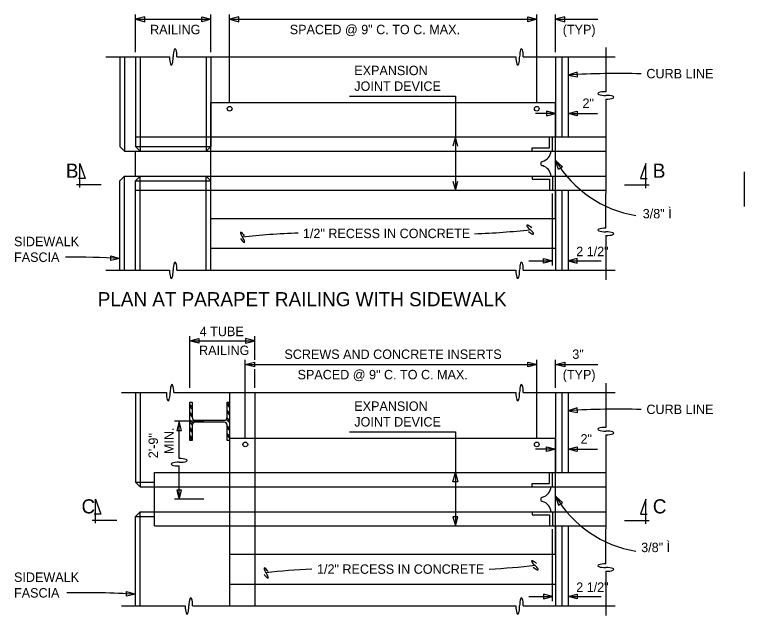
# Model space of a CAD drawing. Extents: x 19590 to 20151, y 19944 to 20103.
# Drawn here: x 19613.3 to 19649.19, y 20048.4 to 20077.92 of the extents above; entities that cross this region are included whole.
import ezdxf

# ---------------------------------------------------------------- set-up
doc = ezdxf.new("R2010")
doc.units = 0
for name, color, linetype in [('DETAIL_PR', 7, 'Continuous'), ('DETAIL_TEXT_DIMEN_PR', 7, 'Continuous'), ('Level 1', 7, 'Continuous'), ('Sheet_Label_Str_Wt0', 7, 'Continuous')]:
    doc.layers.add(name, color=color, linetype=linetype)

msp = doc.modelspace()

# ---------------------------------------------------------------- linework, layer by layer
at = {"layer": 'DETAIL_PR'}
for p, q in [((19642.377, 20076.299), (19642.377, 20074.13)), ((19617.788, 20075.837), (19620.92, 20075.837)), ((19618.481, 20075.837), (19618.481, 20071.443)), ((19618.712, 20075.837), (19618.712, 20071.212)), ((19619.252, 20075.837), (19619.252, 20071.443)), ((19619.483, 20075.837), (19619.483, 20071.212)), ((19621.284, 20075.837), (19637.956, 20075.837)), ((19622.721, 20075.837), (19622.721, 20071.212)), ((19622.952, 20075.837), (19622.952, 20071.443)), ((19638.32, 20075.837), (19642.84, 20075.837)), ((19639.91, 20075.837), (19639.91, 20071.906)), ((19640.219, 20075.837), (19640.219, 20071.906)), ((19640.527, 20075.837), (19640.527, 20071.906)), ((19622.952, 20067.897), (19622.952, 20073.602)), ((19622.952, 20073.602), (19639.91, 20073.602)), ((19639.91, 20067.897), (19639.91, 20073.602)), ((19642.377, 20073.766), (19642.377, 20069.131)), ((19619.252, 20071.906), (19639.91, 20071.906)), ((19639.602, 20071.366), (19639.602, 20071.906)), ((19639.756, 20071.212), (19639.756, 20071.906)), ((19639.91, 20071.906), (19642.377, 20071.906)), ((19618.713, 20071.212), (19618.481, 20071.443)), ((19619.252, 20071.443), (19622.952, 20071.443)), ((19619.483, 20071.212), (19619.252, 20071.443)), ((19622.952, 20071.443), (19622.721, 20071.212)), ((19618.712, 20071.212), (19622.721, 20071.212)), ((19619.252, 20069.979), (19619.252, 20071.212)), ((19622.721, 20071.212), (19642.377, 20071.212)), ((19638.754, 20071.212), (19638.754, 20071.366)), ((19638.754, 20071.366), (19639.602, 20071.366)), ((19649.195, 20068.492), (19649.195, 20070.188)), ((19618.713, 20069.978), (19618.481, 20069.747)), ((19618.481, 20065.354), (19618.481, 20069.747)), ((19618.712, 20069.979), (19622.721, 20069.979)), ((19618.712, 20065.354), (19618.712, 20069.979)), ((19619.483, 20069.978), (19619.252, 20069.747)), ((19619.252, 20069.747), (19622.952, 20069.747)), ((19619.252, 20065.354), (19619.252, 20069.747)), ((19619.483, 20065.354), (19619.483, 20069.979)), ((19622.721, 20069.979), (19642.377, 20069.979)), ((19622.721, 20065.354), (19622.721, 20069.979)), ((19622.952, 20069.747), (19622.721, 20069.979)), ((19622.952, 20065.354), (19622.952, 20069.747)), ((19638.754, 20069.979), (19638.754, 20069.825)), ((19638.754, 20069.824), (19639.602, 20069.824)), ((19639.602, 20069.825), (19639.602, 20069.285)), ((19639.756, 20069.979), (19639.756, 20069.285)), ((19619.252, 20069.285), (19639.91, 20069.285)), ((19639.91, 20069.285), (19639.91, 20065.354)), ((19639.91, 20069.285), (19642.377, 20069.285)), ((19640.219, 20069.285), (19640.219, 20065.354)), ((19640.527, 20069.285), (19640.527, 20065.354)), ((19642.377, 20067.424), (19642.377, 20069.131)), ((19622.952, 20067.897), (19639.91, 20067.897)), ((19642.377, 20067.06), (19642.377, 20064.891)), ((19622.952, 20066.433), (19639.91, 20066.433)), ((19617.788, 20065.353), (19620.92, 20065.353)), ((19621.284, 20065.354), (19637.956, 20065.354)), ((19638.32, 20065.354), (19642.84, 20065.354)), ((19642.377, 20059.804), (19642.377, 20057.634)), ((19618.558, 20059.341), (19620.766, 20059.341)), ((19619.252, 20059.341), (19619.252, 20054.947)), ((19619.483, 20059.341), (19619.483, 20054.716)), ((19621.13, 20059.341), (19637.956, 20059.341)), ((19623.877, 20059.341), (19623.877, 20048.858)), ((19625.11, 20059.341), (19625.11, 20048.858)), ((19638.32, 20059.341), (19642.84, 20059.341)), ((19639.91, 20059.341), (19639.91, 20055.41)), ((19640.219, 20059.341), (19640.219, 20055.41)), ((19640.527, 20059.341), (19640.527, 20055.41)), ((19622.039, 20058.64), (19621.911, 20058.765)), ((19622.039, 20058.539), (19621.911, 20058.677)), ((19623.75, 20058.841), (19623.877, 20058.715)), ((19623.75, 20058.753), (19623.877, 20058.614)), ((19622.039, 20058.161), (19621.911, 20058.299)), ((19622.039, 20058.249), (19621.912, 20058.387)), ((19623.75, 20058.375), (19623.877, 20058.236)), ((19623.751, 20058.463), (19623.878, 20058.337)), ((19622.039, 20057.782), (19621.911, 20057.921)), ((19622.077, 20057.846), (19621.912, 20058.01)), ((19622.165, 20057.984), (19623.623, 20057.984)), ((19623.623, 20057.883), (19622.165, 20057.883)), ((19623.878, 20057.858), (19623.712, 20058.022)), ((19623.75, 20058.085), (19623.877, 20057.947)), ((19622.039, 20057.493), (19621.911, 20057.631)), ((19622.039, 20057.405), (19621.911, 20057.543)), ((19623.75, 20057.707), (19623.878, 20057.568)), ((19623.75, 20057.619), (19623.877, 20057.48)), ((19622.039, 20057.115), (19621.911, 20057.254)), ((19622.039, 20057.027), (19621.911, 20057.153)), ((19623.75, 20057.329), (19623.878, 20057.19)), ((19623.75, 20057.229), (19623.877, 20057.102)), ((19623.877, 20057.106), (19625.11, 20057.106)), ((19625.11, 20057.106), (19639.91, 20057.106)), ((19639.91, 20051.402), (19639.91, 20057.106)), ((19642.377, 20057.271), (19642.377, 20052.635)), ((19620.177, 20052.789), (19620.177, 20055.41)), ((19620.177, 20055.41), (19623.877, 20055.41)), ((19623.877, 20055.41), (19639.91, 20055.41)), ((19639.602, 20054.87), (19639.602, 20055.41)), ((19639.756, 20054.716), (19639.756, 20055.41)), ((19639.91, 20055.41), (19642.377, 20055.41)), ((19619.252, 20054.947), (19620.177, 20054.947)), ((19619.483, 20054.716), (19619.252, 20054.947)), ((19619.483, 20054.716), (19620.177, 20054.716)), ((19620.177, 20054.716), (19623.877, 20054.716)), ((19623.877, 20054.716), (19625.11, 20054.716)), ((19625.11, 20054.716), (19639.91, 20054.716)), ((19638.754, 20054.716), (19638.754, 20054.87)), ((19638.754, 20054.87), (19639.602, 20054.87)), ((19639.91, 20054.716), (19642.377, 20054.716)), ((19619.483, 20053.483), (19619.252, 20053.251)), ((19619.252, 20053.251), (19620.177, 20053.251)), ((19619.252, 20048.858), (19619.252, 20053.251)), ((19619.483, 20053.483), (19620.177, 20053.483)), ((19619.483, 20048.858), (19619.483, 20053.483)), ((19620.177, 20053.483), (19623.877, 20053.483)), ((19623.877, 20053.483), (19625.11, 20053.483)), ((19625.11, 20053.483), (19639.91, 20053.483)), ((19638.754, 20053.483), (19638.754, 20053.329)), ((19638.754, 20053.329), (19639.602, 20053.329)), ((19639.602, 20053.329), (19639.602, 20052.789)), ((19639.756, 20053.483), (19639.756, 20052.789)), ((19639.91, 20053.483), (19642.377, 20053.483)), ((19620.177, 20052.789), (19623.877, 20052.789)), ((19623.877, 20052.789), (19639.91, 20052.789)), ((19639.91, 20052.789), (19642.377, 20052.789)), ((19639.91, 20052.789), (19639.91, 20048.858)), ((19640.219, 20052.789), (19640.219, 20048.858)), ((19640.527, 20052.789), (19640.527, 20048.858)), ((19642.377, 20050.928), (19642.377, 20052.635)), ((19623.877, 20051.402), (19625.11, 20051.402)), ((19625.11, 20051.402), (19639.91, 20051.402)), ((19642.377, 20050.564), (19642.377, 20048.395)), ((19623.877, 20049.937), (19625.11, 20049.937)), ((19625.11, 20049.937), (19639.91, 20049.937)), ((19618.558, 20048.858), (19621.691, 20048.858)), ((19622.055, 20048.858), (19637.956, 20048.858)), ((19638.32, 20048.858), (19642.84, 20048.858))]:
    msp.add_line(p, q, dxfattribs=at)
for points in [[(19622.039, 20057.77), (19622.039, 20056.989), (19621.911, 20056.989), (19621.911, 20058.879), (19622.039, 20058.879), (19622.039, 20058.097)], [(19623.751, 20058.097), (19623.75, 20058.879), (19623.877, 20058.879), (19623.877, 20056.989), (19623.75, 20056.989), (19623.75, 20057.77)]]:
    msp.add_lwpolyline(points, dxfattribs=at)
for centre in [(19623.877, 20073.293), (19638.985, 20073.293), (19624.648, 20056.797), (19638.985, 20056.797)]:
    msp.add_circle(centre, 0.116, dxfattribs=at)
for centre, radius, start, end in [((19639.08, 20071.277), 0.612, 288.1365, 353.9316), ((19639.278, 20070.595), 0.0999, 94.4387, 265.5613), ((19639.08, 20069.914), 0.612, 6.0684, 71.8635), ((19639.08, 20054.781), 0.612, 288.1365, 353.9316), ((19639.278, 20054.1), 0.0999, 94.4387, 265.5613), ((19639.08, 20053.418), 0.612, 6.0684, 71.8635)]:
    msp.add_arc(centre, radius, start, end, dxfattribs=at)
for centre, major_axis, ratio, start_param, end_param in [((19621.193, 20075.837), (0, -0.395), 0.230204, 1.570796, 4.712389), ((19638.229, 20075.837), (0, -0.395), 0.230204, 1.570796, 4.712389), ((19621.011, 20075.837), (0, -0.395), 0.230206, 4.712389, 7.853982), ((19638.047, 20075.837), (0, -0.395), 0.230206, 4.712389, 7.853982), ((19642.377, 20074.039), (0.395, 0), 0.230204, 1.570796, 4.712389), ((19642.377, 20073.857), (0.395, 0), 0.230206, 4.712389, 7.853982), ((19638.697, 20067.398), (0.203, -0.168), 0.230204, 1.570796, 4.712389), ((19624.563, 20067.012), (0.147, -0.219), 0.230204, 1.570796, 4.712389), ((19638.619, 20067.305), (0.203, -0.168), 0.230206, 4.712389, 7.853982), ((19642.377, 20067.333), (0.395, 0), 0.230204, 1.570796, 4.712389), ((19642.377, 20067.151), (0.395, 0), 0.230206, 4.712389, 7.853982), ((19624.462, 20066.945), (0.147, -0.219), 0.230206, 4.712389, 7.853982), ((19621.193, 20065.353), (0, -0.395), 0.230204, 1.570796, 4.712389), ((19638.229, 20065.354), (0, -0.395), 0.230204, 1.570796, 4.712389), ((19621.011, 20065.353), (0, -0.395), 0.230206, 4.712389, 7.853982), ((19638.047, 20065.354), (0, -0.395), 0.230206, 4.712389, 7.853982), ((19621.039, 20059.341), (0, -0.395), 0.230204, 1.570796, 4.712389), ((19638.229, 20059.341), (0, -0.395), 0.230204, 1.570796, 4.712389), ((19620.857, 20059.341), (0, -0.395), 0.230206, 4.712389, 7.853982), ((19638.047, 20059.341), (0, -0.395), 0.230206, 4.712389, 7.853982), ((19622.16, 20058.098), (0.116, 0), 0.993605, 3.141593, 4.712389), ((19622.16, 20057.771), (0.116, 0), 0.993605, 1.570796, 3.141593), ((19623.629, 20058.098), (0.116, 0), 0.993605, 4.712389, 6.283185), ((19623.629, 20057.771), (0.116, 0), 0.993605, 0, 1.570796), ((19642.377, 20057.543), (0.395, 0), 0.230204, 1.570796, 4.712389), ((19642.377, 20057.362), (0.395, 0), 0.230206, 4.712389, 7.853982), ((19638.928, 20050.902), (0.203, -0.168), 0.230204, 1.570796, 4.712389), ((19625.719, 20050.516), (0.147, -0.219), 0.230204, 1.570796, 4.712389), ((19638.851, 20050.809), (0.203, -0.168), 0.230206, 4.712389, 7.853982), ((19642.377, 20050.837), (0.395, 0), 0.230204, 1.570796, 4.712389), ((19642.377, 20050.655), (0.395, 0), 0.230206, 4.712389, 7.853982), ((19625.619, 20050.449), (0.147, -0.219), 0.230206, 4.712389, 7.853982), ((19621.964, 20048.858), (0, -0.395), 0.230204, 1.570796, 4.712389), ((19638.229, 20048.858), (0, -0.395), 0.230204, 1.570796, 4.712389), ((19621.782, 20048.858), (0, -0.395), 0.230206, 4.712389, 7.853982), ((19638.047, 20048.858), (0, -0.395), 0.230206, 4.712389, 7.853982)]:
    msp.add_ellipse(centre, major_axis=major_axis, ratio=ratio, start_param=start_param, end_param=end_param, dxfattribs=at)
at = {"layer": 'DETAIL_TEXT_DIMEN_PR'}
for p, q in [((19619.252, 20076.068), (19619.252, 20077.918)), ((19622.952, 20076.068), (19622.952, 20077.918)), ((19623.877, 20073.602), (19623.877, 20077.918)), ((19638.985, 20073.602), (19638.985, 20077.918)), ((19639.91, 20076.068), (19639.91, 20077.918)), ((19619.252, 20077.687), (19622.952, 20077.687)), ((19623.877, 20077.687), (19638.985, 20077.687)), ((19639.91, 20077.687), (19641.992, 20077.687)), ((19629.765, 20073.91), (19634.977, 20073.91)), ((19634.977, 20073.91), (19634.977, 20069.285)), ((19639.91, 20073.062), (19638.928, 20073.062)), ((19640.527, 20073.062), (19641.972, 20073.062)), ((19616.516, 20069.424), (19616.516, 20070.595)), ((19616.516, 20070.595), (19616.768, 20069.859)), ((19644.343, 20070.595), (19644.089, 20069.859)), ((19644.342, 20069.397), (19644.343, 20070.595)), ((19616.768, 20069.859), (19616.438, 20069.859)), ((19644.089, 20069.859), (19644.42, 20069.859)), ((19617.556, 20069.555), (19616.35, 20069.555)), ((19643.302, 20069.555), (19644.518, 20069.555)), ((19639.756, 20065.585), (19639.756, 20069.131)), ((19638.6, 20065.816), (19639.756, 20065.816)), ((19640.527, 20065.816), (19642.146, 20065.816)), ((19621.911, 20059.572), (19621.911, 20062.116)), ((19625.11, 20060.96), (19625.11, 20062.116)), ((19621.911, 20061.885), (19625.11, 20061.885)), ((19624.648, 20057.106), (19624.648, 20060.96)), ((19624.648, 20060.729), (19638.985, 20060.729)), ((19638.985, 20057.106), (19638.985, 20060.96)), ((19639.91, 20059.572), (19639.91, 20060.96)), ((19639.91, 20060.729), (19641.992, 20060.729)), ((19625.11, 20059.572), (19625.11, 20060.497)), ((19622.6, 20057.934), (19621.16, 20057.934)), ((19621.392, 20056.102), (19621.392, 20057.934)), ((19629.765, 20057.414), (19634.977, 20057.414)), ((19634.977, 20057.414), (19634.977, 20052.789)), ((19639.91, 20056.566), (19638.928, 20056.566)), ((19640.527, 20056.566), (19641.972, 20056.566)), ((19621.392, 20054.099), (19621.392, 20055.738)), ((19617.287, 20052.928), (19617.286, 20054.099)), ((19617.286, 20054.099), (19617.539, 20053.363)), ((19622.6, 20054.099), (19621.16, 20054.099)), ((19644.343, 20054.099), (19644.089, 20053.363)), ((19644.342, 20052.901), (19644.343, 20054.099)), ((19617.539, 20053.363), (19617.209, 20053.363)), ((19644.089, 20053.363), (19644.42, 20053.363)), ((19618.327, 20053.059), (19617.121, 20053.059)), ((19643.302, 20053.059), (19644.518, 20053.059)), ((19639.756, 20049.089), (19639.756, 20052.635)), ((19638.6, 20049.32), (19639.756, 20049.32)), ((19640.527, 20049.32), (19642.146, 20049.32))]:
    msp.add_line(p, q, dxfattribs=at)
for centre, start, end in [((19642.954, 20035.872), 88.2954, 93.5535), ((19616.055, 20026.854), 86.4465, 90.3732), ((19642.954, 20019.377), 88.2954, 93.5535), ((19616.825, 20010.358), 86.4465, 91.4029)]:
    msp.add_arc(centre, 39.151, start, end, dxfattribs=at)
for centre, ratio, start_param, end_param in [((19621.392, 20056.011), 0.230206, 1.570796, 4.712389), ((19621.392, 20055.829), 0.230204, 4.712389, 7.853982)]:
    msp.add_ellipse(centre, major_axis=(-0.395, 0), ratio=ratio, start_param=start_param, end_param=end_param, dxfattribs=at)
at = {"layer": 'Level 1'}
for p, q in [((19619.7, 20077.802), (19619.252, 20077.687)), ((19619.252, 20077.687), (19619.7, 20077.571)), ((19619.7, 20077.571), (19619.7, 20077.802)), ((19622.504, 20077.571), (19622.504, 20077.802)), ((19622.504, 20077.802), (19622.952, 20077.687)), ((19622.952, 20077.687), (19622.504, 20077.571)), ((19624.325, 20077.803), (19623.877, 20077.687)), ((19623.877, 20077.687), (19624.325, 20077.571)), ((19624.325, 20077.571), (19624.325, 20077.803)), ((19638.537, 20077.571), (19638.537, 20077.803)), ((19638.537, 20077.803), (19638.985, 20077.687)), ((19638.985, 20077.687), (19638.537, 20077.571)), ((19640.358, 20077.803), (19639.91, 20077.687)), ((19639.91, 20077.687), (19640.358, 20077.571)), ((19640.358, 20077.571), (19640.358, 20077.803)), ((19640.968, 20075.089), (19640.527, 20074.949)), ((19640.981, 20074.858), (19640.968, 20075.089)), ((19640.527, 20074.949), (19640.981, 20074.858)), ((19639.91, 20073.062), (19639.463, 20073.178)), ((19639.463, 20073.178), (19639.463, 20072.946)), ((19639.463, 20072.946), (19639.91, 20073.062)), ((19640.527, 20073.062), (19640.975, 20073.177)), ((19640.975, 20072.946), (19640.527, 20073.062)), ((19640.975, 20073.177), (19640.975, 20072.946)), ((19634.977, 20071.906), (19634.861, 20071.458)), ((19635.093, 20071.458), (19634.977, 20071.906)), ((19639.91, 20070.749), (19640.247, 20070.432)), ((19640.051, 20070.309), (19639.91, 20070.749)), ((19640.247, 20070.432), (19640.051, 20070.309)), ((19634.861, 20069.733), (19634.977, 20069.285)), ((19634.977, 20069.285), (19635.093, 20069.733)), ((19618.027, 20065.839), (19618.04, 20066.07)), ((19618.04, 20066.07), (19618.481, 20065.93)), ((19618.481, 20065.93), (19618.027, 20065.839)), ((19639.308, 20065.7), (19639.308, 20065.932)), ((19639.308, 20065.932), (19639.756, 20065.816)), ((19639.756, 20065.816), (19639.308, 20065.7)), ((19640.975, 20065.932), (19640.527, 20065.816)), ((19640.527, 20065.816), (19640.975, 20065.7)), ((19640.975, 20065.7), (19640.975, 20065.932)), ((19621.911, 20061.885), (19622.359, 20062)), ((19622.359, 20061.769), (19621.911, 20061.885)), ((19622.359, 20062), (19622.359, 20061.769)), ((19625.11, 20061.885), (19624.662, 20062)), ((19624.662, 20062), (19624.662, 20061.769)), ((19624.662, 20061.769), (19625.11, 20061.885)), ((19624.648, 20060.729), (19625.096, 20060.844)), ((19625.096, 20060.613), (19624.648, 20060.729)), ((19625.096, 20060.844), (19625.096, 20060.613)), ((19638.537, 20060.613), (19638.537, 20060.844)), ((19638.537, 20060.844), (19638.985, 20060.729)), ((19638.985, 20060.729), (19638.537, 20060.613)), ((19639.91, 20060.729), (19640.358, 20060.844)), ((19640.358, 20060.613), (19639.91, 20060.729)), ((19640.358, 20060.844), (19640.358, 20060.613)), ((19640.968, 20058.593), (19640.527, 20058.453)), ((19640.981, 20058.362), (19640.968, 20058.593)), ((19640.527, 20058.453), (19640.981, 20058.362)), ((19621.392, 20057.934), (19621.276, 20057.486)), ((19621.507, 20057.486), (19621.392, 20057.934)), ((19621.276, 20057.486), (19621.507, 20057.486)), ((19639.463, 20056.682), (19639.91, 20056.566)), ((19639.463, 20056.45), (19639.463, 20056.682)), ((19639.91, 20056.566), (19639.463, 20056.45)), ((19640.527, 20056.566), (19640.975, 20056.682)), ((19640.975, 20056.45), (19640.527, 20056.566)), ((19640.975, 20056.682), (19640.975, 20056.45)), ((19634.861, 20054.962), (19634.977, 20055.41)), ((19634.977, 20055.41), (19635.093, 20054.962)), ((19635.093, 20054.962), (19634.861, 20054.962)), ((19621.507, 20054.548), (19621.276, 20054.548)), ((19621.276, 20054.548), (19621.392, 20054.099)), ((19621.392, 20054.099), (19621.507, 20054.548)), ((19640.247, 20053.936), (19639.91, 20054.254)), ((19639.91, 20054.254), (19640.051, 20053.813)), ((19640.051, 20053.813), (19640.247, 20053.936)), ((19635.093, 20053.237), (19634.861, 20053.237)), ((19634.861, 20053.237), (19634.977, 20052.789)), ((19634.977, 20052.789), (19635.093, 20053.237)), ((19618.798, 20049.343), (19618.811, 20049.575)), ((19618.811, 20049.575), (19619.252, 20049.434)), ((19619.252, 20049.434), (19618.798, 20049.343)), ((19639.756, 20049.32), (19639.308, 20049.436)), ((19639.308, 20049.436), (19639.308, 20049.205)), ((19639.308, 20049.205), (19639.756, 20049.32)), ((19640.527, 20049.32), (19640.975, 20049.436)), ((19640.975, 20049.205), (19640.527, 20049.32)), ((19640.975, 20049.436), (19640.975, 20049.205))]:
    msp.add_line(p, q, dxfattribs=at)
for centre in [(19644.756, 20073.599), (19644.756, 20057.103)]:
    msp.add_arc(centre, 5.621, 210.4552, 260.8059, dxfattribs=at)
for centre, major_axis, start_param in [((19627.415, 20066.075), (-6.57, -0.223), 4.731306), ((19635.756, 20068.255), (6.57, 0.223), 4.731306), ((19628.571, 20049.586), (-6.57, -0.223), 4.805942), ((19635.987, 20051.759), (6.57, 0.223), 4.805942)]:
    msp.add_ellipse(centre, major_axis=major_axis, ratio=0.169331, start_param=start_param, end_param=5.164147, dxfattribs=at)

# ---------------------------------------------------------------- texts
at = {"layer": 'DETAIL_TEXT_DIMEN_PR'}
for s, height, p in [('RAILING', 0.4625, (19619.963, 20076.955)), ('SPACED @ 9" C. TO C. MAX.', 0.4625, (19626.833, 20076.955)), ('(TYP)', 0.4625, (19640.259, 20076.955)), ('EXPANSION ', 0.4625, (19630.007, 20074.943)), ('CURB LINE', 0.4625, (19644.376, 20074.786)), ('JOINT DEVICE', 0.4625, (19630.007, 20074.172)), ('2"', 0.4625, (19641.232, 20073.332)), ('B', 0.694, (19615.822, 20069.901)), ('B', 0.694, (19644.69, 20069.901)), ('1/2" RECESS IN CONCRETE', 0.4625, (19627.481, 20066.934)), ('SIDEWALK', 0.4625, (19613.272, 20066.538)), ('2 1/2"', 0.4625, (19640.923, 20066.047)), ('FASCIA', 0.4625, (19613.272, 20065.767)), ('PLAN AT PARAPET RAILING WITH SIDEWALK', 0.69385, (19617.39, 20063.586)), ('4 TUBE', 0.4625, (19622.404, 20062.116)), ('RAILING', 0.4625, (19622.372, 20061.191)), ('SCREWS AND CONCRETE INSERTS', 0.4625, (19626.57, 20060.998)), ('3"', 0.4625, (19640.73, 20060.998)), ('SPACED @ 9" C. TO C. MAX.', 0.4625, (19627.218, 20059.996)), ('(TYP)', 0.4625, (19640.259, 20059.996)), ('EXPANSION ', 0.4625, (19630.007, 20058.447)), ('CURB LINE', 0.4625, (19644.376, 20058.29)), ('JOINT DEVICE', 0.4625, (19630.007, 20057.676)), ('2"', 0.4625, (19641.135, 20056.837)), ('C', 0.694, (19616.593, 20053.406)), ('C', 0.694, (19644.69, 20053.406)), ('1/2" RECESS IN CONCRETE', 0.4625, (19628.174, 20050.438)), ('SIDEWALK', 0.4625, (19613.272, 20050.042)), ('2 1/2"', 0.4625, (19640.923, 20049.551)), ('FASCIA', 0.4625, (19613.272, 20049.272))]:
    msp.add_text(s, height=height, dxfattribs=at).set_placement(p)
for s, p in [('MIN.', (19621.122, 20056.32)), ('2\'-9"', (19620.351, 20056.12))]:
    msp.add_text(s, height=0.4625, rotation=90, dxfattribs=at).set_placement(p)
at = {"layer": 'Sheet_Label_Str_Wt0'}
for p in [(19644.195, 20067.905), (19644.118, 20051.504)]:
    msp.add_text('3/8" Ì', height=0.4625, dxfattribs=at).set_placement(p)

doc.saveas('drawing.dxf')
